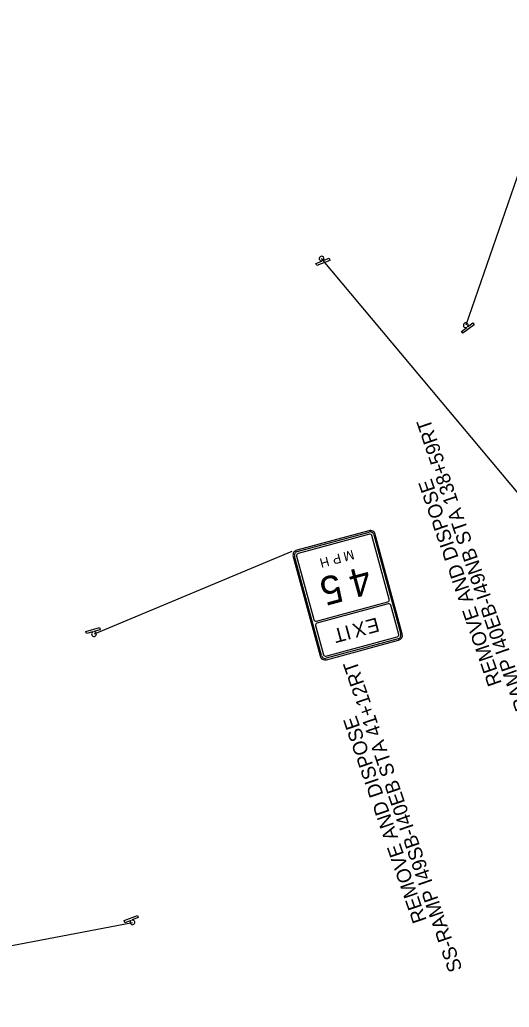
# Model space of a CAD drawing. Extents: x 641128 to 649424, y 422807 to 432853.
# Drawn here: x 644486 to 644900, y 426524 to 427359 of the extents above; entities that cross this region are included whole.
import ezdxf

# ---------------------------------------------------------------- set-up
doc = ezdxf.new("R2010")
doc.units = 0
doc.layers.add('R_Dimension_2', color=7, linetype='Continuous')
doc.layers.add('S_SIGN', color=7, linetype='Continuous')

msp = doc.modelspace()

# ---------------------------------------------------------------- linework, layer by layer
at = {"layer": 'S_SIGN'}
for p, q in [((644952.77, 427359.18), (644863.5, 427100.82)), ((644736.73, 427153.1), (644741.93, 427155.11)), ((644748.65, 427155.56), (644737.45, 427151.24)), ((644943.96, 426915.54), (644741.61, 427157.13)), ((644741.93, 427155.11), (644741.91, 427155.15)), ((644742.75, 427155.49), (644742.78, 427155.44)), ((644742.78, 427155.44), (644747.93, 427157.43)), ((644747.93, 427157.43), (644748.65, 427155.56)), ((644737.45, 427151.24), (644736.73, 427153.1)), ((644859.86, 427095.65), (644864.35, 427098.96)), ((644861.05, 427094.04), (644859.86, 427095.65)), ((644870.71, 427101.16), (644861.05, 427094.04)), ((644864.35, 427098.96), (644864.32, 427098.99)), ((644865.04, 427099.54), (644865.08, 427099.49)), ((644865.08, 427099.49), (644869.52, 427102.77)), ((644869.52, 427102.77), (644870.71, 427101.16)), ((644781.51, 426927.06), (644720.7, 426910.6)), ((644809.77, 426839.92), (644787.03, 426923.9)), ((644716.35, 426909.42), (644549.12, 426839.62)), ((644717.53, 426905.08), (644740.27, 426821.1)), ((644542.28, 426841.92), (644553.87, 426845.05)), ((644553.87, 426845.05), (644554.39, 426843.12)), ((644542.81, 426839.99), (644542.28, 426841.92)), ((644548.14, 426841.43), (644542.81, 426839.99)), ((644548.15, 426841.37), (644548.14, 426841.43)), ((644554.39, 426843.12), (644549.01, 426841.67)), ((644549.01, 426841.67), (644549.02, 426841.62)), ((644745.79, 426817.94), (644806.6, 426834.4)), ((644206, 426524), (644581.64, 426595.78)), ((644574.59, 426597.33), (644585.77, 426601.69)), ((644575.32, 426595.47), (644574.59, 426597.33)), ((644580.46, 426597.47), (644575.32, 426595.47)), ((644580.48, 426597.42), (644580.46, 426597.47)), ((644586.5, 426599.82), (644581.31, 426597.8)), ((644581.31, 426597.8), (644581.32, 426597.76)), ((644585.77, 426601.69), (644586.5, 426599.82))]:
    msp.add_line(p, q, dxfattribs=at)
for points in [[(644781.51, 426927.06), (644720.7, 426910.6)], [(644721.03, 426909.39), (644781.84, 426925.86)], [(644782.05, 426924.1), (644721.72, 426907.77)], [(644781.51, 426927.06), (644781.51, 426927.06), (644781.51, 426927.06)], [(644782.05, 426924.1), (644782.05, 426924.1), (644782.05, 426924.1)], [(644798.77, 426869.06), (644784.2, 426922.87)], [(644785.82, 426923.57), (644808.56, 426839.59)], [(644809.77, 426839.92), (644787.03, 426923.9)], [(644717.53, 426905.08), (644740.27, 426821.1)], [(644717.53, 426905.08), (644717.53, 426905.08), (644717.53, 426905.08)], [(644741.47, 426821.43), (644718.74, 426905.41)], [(644720.49, 426905.62), (644735.06, 426851.81)], [(644737.21, 426850.58), (644797.54, 426866.91)], [(644797.99, 426865.22), (644737.67, 426848.89)], [(644797.99, 426865.22), (644797.99, 426865.22), (644797.99, 426865.22)], [(644806.8, 426839.38), (644800.14, 426863.99)], [(644736.43, 426846.74), (644743.1, 426822.13)], [(644745.24, 426820.9), (644805.57, 426837.23)], [(644809.77, 426839.92), (644809.77, 426839.92), (644809.77, 426839.92)], [(644806.27, 426835.61), (644745.46, 426819.14)], [(644745.79, 426817.94), (644806.6, 426834.4)], [(644745.79, 426817.94), (644745.79, 426817.94), (644745.79, 426817.94)]]:
    msp.add_lwpolyline(points, dxfattribs=at)
for centre, radius, start, end in [((644741.61, 427157.13), 2, 21.1275, 278.80759), ((644741.61, 427157.13), 2, 304.98962, 21.1275), ((644863.5, 427100.82), 2, 36.38264, 294.06274), ((644863.5, 427100.82), 2, 320.24477, 36.38264), ((644782.69, 426922.72), 4.5, 15.14945, 105.14966), ((644782.69, 426922.72), 4.5, 15.14945, 105.14966), ((644782.69, 426922.72), 3.25, 15.14945, 105.14966), ((644782.51, 426922.41), 1.75, 15.14945, 105.14966), ((644721.87, 426906.26), 4.5, 105.14966, 195.14987), ((644721.87, 426906.26), 4.5, 105.14966, 195.14987), ((644721.87, 426906.26), 3.25, 105.14966, 195.14987), ((644722.18, 426906.08), 1.75, 105.14966, 195.14987), ((644797.08, 426868.6), 1.75, 285.14981, 15.14945), ((644798.45, 426863.53), 1.75, 15.14945, 105.14966), ((644736.75, 426852.27), 1.75, 195.1496, 285.14981), ((644738.12, 426847.2), 1.75, 105.14966, 195.14987), ((644549.12, 426839.62), 2, 119.01172, 195.1496), ((644549.12, 426839.62), 2, 195.1496, 92.82969), ((644805.12, 426838.92), 1.75, 285.14981, 15.14945), ((644805.42, 426838.74), 3.25, 285.14981, 15.14945), ((644805.42, 426838.74), 4.5, 285.14981, 15.14945), ((644805.42, 426838.74), 4.5, 285.14981, 15.14945), ((644744.61, 426822.28), 4.5, 195.1496, 285.14981), ((644744.61, 426822.28), 4.5, 195.1496, 285.14981), ((644744.61, 426822.28), 3.25, 195.1496, 285.14981), ((644744.79, 426822.59), 1.75, 195.1496, 285.14981), ((644581.64, 426595.78), 2, 125.14865, 201.28652), ((644581.64, 426595.78), 2, 201.28652, 98.96662)]:
    msp.add_arc(centre, radius, start, end, dxfattribs=at)

# ---------------------------------------------------------------- texts
at = {"layer": 'R_Dimension_2'}
for s, p in [('SS-RAMP I40EB-I49NB STA 138+59RT', (644926.12, 426751.58)), ('REMOVE AND DISPOSE', (644894.13, 426798.02))]:
    msp.add_text(s, height=12, rotation=108.95522, dxfattribs=at).set_placement(p)
at = {"layer": 'S_SIGN'}
for s, height, rotation, p in [('H', 8, 195.1496, (644746.76, 426905.22)), ('P', 8, 195.1496, (644756.83, 426907.95)), ('M', 8, 195.1496, (644767.87, 426910.94)), ('4', 24, 195.1496, (644779.87, 426897.61)), ('5', 24, 195.1496, (644755.44, 426891)), ('E', 12, 195.1496, (644788.33, 426853.8)), ('T', 12, 195.1496, (644759.8, 426846.08)), ('I', 12, 195.1496, (644764.48, 426847.34)), ('X', 12, 195.1496, (644777.13, 426850.77)), ('SS-RAMP I49SB-I40EB STA 41+12RT', 12, 108.95522, (644860.79, 426556.21)), ('REMOVE AND DISPOSE', 12, 108.95522, (644830.54, 426597.59))]:
    msp.add_text(s, height=height, rotation=rotation, dxfattribs=at).set_placement(p)

doc.saveas('drawing.dxf')
